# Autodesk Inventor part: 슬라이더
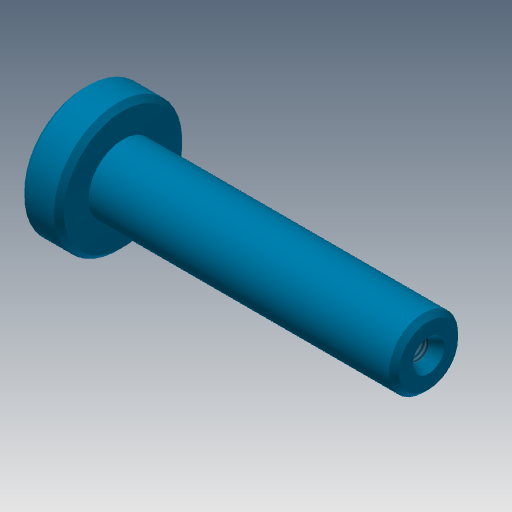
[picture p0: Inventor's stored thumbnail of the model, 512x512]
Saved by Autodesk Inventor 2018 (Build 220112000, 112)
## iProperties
Created: 2019-01
Part Number: 슬라이더
Material: 강철, 연강
Document SubType Name: Modeling
Designer: mduedu
Density: 7.86 g/cm^3
Appearance: 하늘색 중간
Mass: 105.846 g
Surface Area: 45.0711 cm^2
Volume: 13.4664 cm^3
Author: mduedu
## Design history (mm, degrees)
sketch "스케치1"
  geometry: L1 (0, 0)-(8, 0); L2 (8, 0)-(8, 13); L3 (8, 13)-(0, 13); L4 (0, 13)-(0, 0); L5 (8, 0)-(70, 0); L6 (70, 0)-(70, 7); L7 (70, 7)-(8, 7); L8 (8, 7)-(8, 0)
  constraints: 16 end point, 4 parallel, 2 horizontal, 2 perpendicular
  dimensions: "d0" = 70 distance between parallel lines of L6 L4; "d2" = 8 distance of L2.end L3.end; "d3" = 26 diameter of L3 L1; "d4" = 14 diameter of L7 L5
revolve "회전1" sketch "스케치1" stored, may be unused: angle "d5" = 90 deg
chamfer "모따기1" distance "d6" = 1; stored, may be unused: second distance "d7" = 2, angle "d8" = 45 deg
hole "구멍1" diameter "d14" = 4.134; stored, may be unused: countersink angle "d18" = 60 deg, drill point angle "d20" = 118 deg; dims "d15" = 12, "d16" = 6.3, "d17" = 2, "d19" = 15, "d26" = 10, "d27" = 10
chamfer "모따기4" distance "d24" = 1; stored, may be unused: second distance "d25" = 2, angle "d28" = 30 deg
sketch "스케치2"
  geometry: L1 (70, 2.067)-(70, -2.067) reference; L2 (70, 0)-(68, 0); L3 (68, 0)-(68, 2.067); L4 (70, 3.222)-(70, 0); L5 (70, 3.222)-(68, 2.067); L6 (55, 2.067)-(70, 2.067) reference; 1 further point
  constraints: 8 end point, 1 horizontal, 1 midpoint, 1 parallel, 1 perpendicular, 1 point on line
  dimensions: "d29" = 2 horizontal distance of L4.start L3.end; "d31" = 30 deg angle of L2 L5
revolve "회전2" sketch "스케치2" stored, may be unused: angle "d33" = 90 deg
node "솔리드1"
